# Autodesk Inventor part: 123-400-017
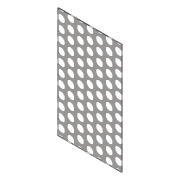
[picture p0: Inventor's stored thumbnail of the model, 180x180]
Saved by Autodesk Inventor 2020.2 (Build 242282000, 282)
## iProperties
Manager: www.cadconsulting.pl
Company: Fabian Stasiak CAD Consulting
Created: 2019-11
Part Number: 123-400-017
Material: Stal
Document SubType Name: Modeling
Designer: F.Stasiak
Density: 7.85 g/cm^3
Appearance: Stal — polerowana
Description: Płyta perforowana
Author: F.Stasiak
Subject: Zbiór ćwiczeń. Autodesk Inventor 2020. Kurs podstawowy
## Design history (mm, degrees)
sketch "Szkic1"
  geometry: L1 (-170, -295)-(170, -295); L2 (170, -295)-(170, 295); L3 (170, 295)-(-170, 295); L4 (-170, 295)-(-170, -295); L5 (-170, -295)-(170, 295); L6 (170, -295)-(-170, 295); 1 further point
  constraints: 12 end point, 2 midpoint, 2 parallel, 1 horizontal, 1 perpendicular
  dimensions: "d0" = 590 distance of L1.end L2.end; "d1" = 340 distance of L2.end L3.end
extrude "Wyciągnięcie proste1" new body sketch "Szkic1" distance "d2" = 5; taper "d3" = 0 deg
node "Bryła1"
